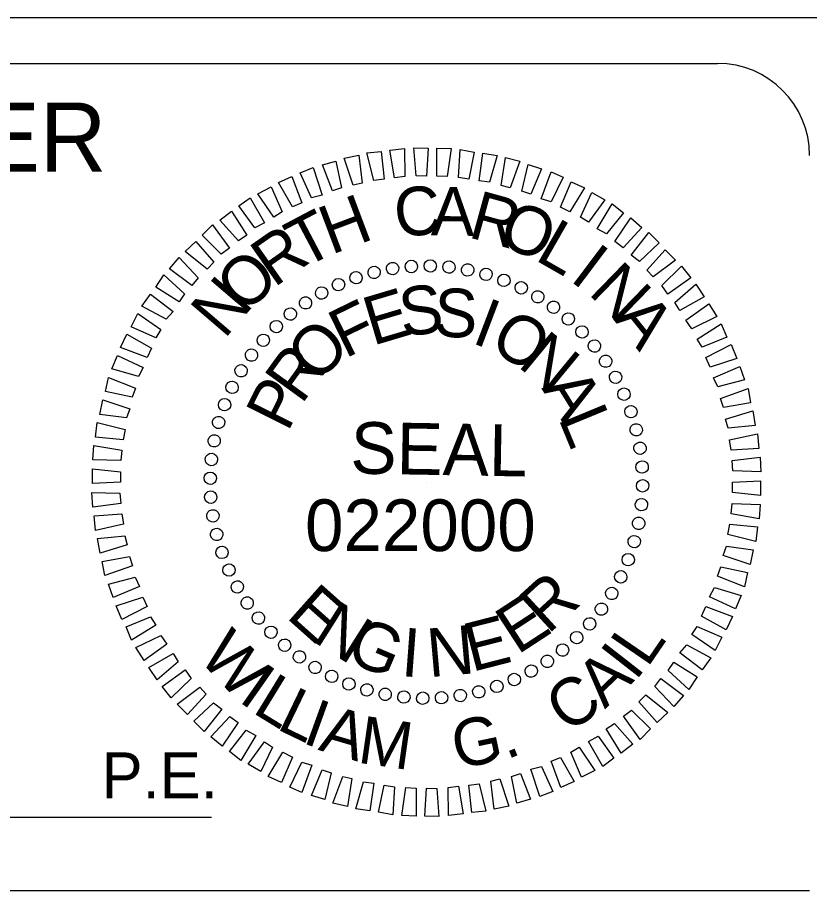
# Model space of a CAD drawing. Extents: x 2163579 to 2286010, y 210234 to 425257.
# Drawn here: x 2253219 to 2258732, y 338718 to 344796 of the extents above; entities that cross this region are included whole.
import ezdxf

# ---------------------------------------------------------------- set-up
doc = ezdxf.new("R2010")
doc.units = 0
doc.layers.add('Sheet Professional Seal CELL', color=7, linetype='Continuous')
doc.layers.add('Sheet Title CELL', color=7, linetype='Continuous')

msp = doc.modelspace()

# ---------------------------------------------------------------- linework, layer by layer
at = {"layer": 'Sheet Professional Seal CELL'}
for p, q in [((2255700, 343022.5), (2255700, 343022.5)), ((2255832, 343046.5), (2255832, 343046.5)), ((2255961, 343064.5), (2255961, 343064.5)), ((2256093, 343067.5), (2256093, 343067.5)), ((2256225, 343058.5), (2256225, 343058.5)), ((2256354, 343037.5), (2256354, 343037.5)), ((2256480, 343010.5), (2256480, 343010.5)), ((2255574, 342986.5), (2255574, 342986.5)), ((2256606, 342968.5), (2256606, 342968.5)), ((2255454, 342938.5), (2255454, 342938.5)), ((2256726, 342914.5), (2256726, 342914.5)), ((2255337, 342878.5), (2255337, 342878.5)), ((2256843, 342854.5), (2256843, 342854.5)), ((2255223, 342809.5), (2255223, 342809.5)), ((2256951, 342779.5), (2256951, 342779.5)), ((2255118, 342734.5), (2255118, 342734.5)), ((2255019, 342644.5), (2255019, 342644.5)), ((2257056, 342698.5), (2257056, 342698.5)), ((2257149, 342608.5), (2257149, 342608.5)), ((2254929, 342551.5), (2254929, 342551.5)), ((2257239, 342509.5), (2257239, 342509.5)), ((2254848, 342446.5), (2254848, 342446.5)), ((2257314, 342404.5), (2257314, 342404.5)), ((2254773, 342338.5), (2254773, 342338.5)), ((2257383, 342290.5), (2257383, 342290.5)), ((2254713, 342221.5), (2254713, 342221.5)), ((2257443, 342173.5), (2257443, 342173.5)), ((2254659, 342101.5), (2254659, 342101.5)), ((2257491, 342053.5), (2257491, 342053.5)), ((2254617, 341975.5), (2254617, 341975.5)), ((2257527, 341927.5), (2257527, 341927.5)), ((2254590, 341849.5), (2254590, 341849.5)), ((2257551, 341795.5), (2257551, 341795.5)), ((2254569, 341720.5), (2254569, 341720.5)), ((2257569, 341666.5), (2257569, 341666.5)), ((2254560, 341588.5), (2254560, 341588.5)), ((2256066, 341561.5), (2256066, 341561.5)), ((2257572, 341534.5), (2257572, 341534.5)), ((2254563, 341456.5), (2254563, 341456.5)), ((2257563, 341402.5), (2257563, 341402.5)), ((2254581, 341327.5), (2254581, 341327.5)), ((2257542, 341273.5), (2257542, 341273.5)), ((2254605, 341195.5), (2254605, 341195.5)), ((2257515, 341147.5), (2257515, 341147.5)), ((2254641, 341069.5), (2254641, 341069.5)), ((2257473, 341021.5), (2257473, 341021.5)), ((2254689, 340949.5), (2254689, 340949.5)), ((2257419, 340901.5), (2257419, 340901.5)), ((2254749, 340832.5), (2254749, 340832.5)), ((2257359, 340784.5), (2257359, 340784.5)), ((2254818, 340718.5), (2254818, 340718.5)), ((2257284, 340676.5), (2257284, 340676.5)), ((2254893, 340613.5), (2254893, 340613.5)), ((2257203, 340571.5), (2257203, 340571.5)), ((2254983, 340514.5), (2254983, 340514.5)), ((2257113, 340478.5), (2257113, 340478.5)), ((2255076, 340424.5), (2255076, 340424.5)), ((2255181, 340343.5), (2255181, 340343.5)), ((2257014, 340388.5), (2257014, 340388.5)), ((2256909, 340313.5), (2256909, 340313.5)), ((2255289, 340268.5), (2255289, 340268.5)), ((2256795, 340244.5), (2256795, 340244.5)), ((2255406, 340208.5), (2255406, 340208.5)), ((2255526, 340154.5), (2255526, 340154.5)), ((2256678, 340184.5), (2256678, 340184.5)), ((2255652, 340112.5), (2255652, 340112.5)), ((2256432, 340100.5), (2256432, 340100.5)), ((2256558, 340136.5), (2256558, 340136.5)), ((2255778, 340085.5), (2255778, 340085.5)), ((2255907, 340064.5), (2255907, 340064.5)), ((2256039, 340055.5), (2256039, 340055.5)), ((2256171, 340058.5), (2256171, 340058.5)), ((2256300, 340076.5), (2256300, 340076.5))]:
    msp.add_line(p, q, dxfattribs=at)
for points in [[(2255700, 343661.5), (2255652, 343853.5), (2255751, 343862.5), (2255772, 343670.5)], [(2255844, 343679.5), (2255811, 343871.5), (2255913, 343883.5), (2255916, 343688.5)], [(2255994, 343694.5), (2255979, 343889.5), (2256078, 343886.5), (2256066, 343691.5)], [(2256138, 343691.5), (2256138, 343886.5), (2256237, 343883.5), (2256210, 343688.5)], [(2256288, 343682.5), (2256300, 343877.5), (2256399, 343859.5), (2256360, 343670.5)], [(2255556, 343628.5), (2255493, 343817.5), (2255595, 343838.5), (2255619, 343643.5)], [(2256432, 343658.5), (2256459, 343850.5), (2256558, 343835.5), (2256504, 343649.5)], [(2256585, 343625.5), (2256615, 343820.5), (2256717, 343796.5), (2256648, 343610.5)], [(2255265, 343541.5), (2255187, 343715.5), (2255277, 343751.5), (2255340, 343559.5)], [(2255412, 343589.5), (2255343, 343769.5), (2255436, 343796.5), (2255475, 343610.5)], [(2256729, 343586.5), (2256774, 343772.5), (2256867, 343742.5), (2256792, 343565.5)], [(2255133, 343478.5), (2255037, 343646.5), (2255130, 343688.5), (2255199, 343505.5)], [(2256864, 343532.5), (2256933, 343721.5), (2257017, 343685.5), (2256933, 343511.5)], [(2255004, 343406.5), (2254893, 343568.5), (2254986, 343616.5), (2255061, 343442.5)], [(2256999, 343475.5), (2257074, 343652.5), (2257167, 343610.5), (2257065, 343442.5)], [(2257137, 343406.5), (2257218, 343577.5), (2257308, 343526.5), (2257194, 343370.5)], [(2254872, 343331.5), (2254761, 343484.5), (2254839, 343541.5), (2254938, 343367.5)], [(2257254, 343325.5), (2257359, 343499.5), (2257437, 343436.5), (2257320, 343289.5)], [(2254758, 343241.5), (2254629, 343385.5), (2254710, 343448.5), (2254815, 343280.5)], [(2257377, 343235.5), (2257488, 343400.5), (2257566, 343334.5), (2257434, 343193.5)], [(2254638, 343148.5), (2254506, 343280.5), (2254578, 343352.5), (2254695, 343190.5)], [(2257491, 343142.5), (2257614, 343298.5), (2257686, 343226.5), (2257548, 343097.5)], [(2254539, 343043.5), (2254386, 343166.5), (2254461, 343235.5), (2254587, 343091.5)], [(2257599, 343037.5), (2257728, 343178.5), (2257800, 343106.5), (2257644, 342989.5)], [(2254434, 342929.5), (2254278, 343046.5), (2254344, 343124.5), (2254476, 342983.5)], [(2257704, 342929.5), (2257842, 343064.5), (2257905, 342983.5), (2257746, 342869.5)], [(2254344, 342815.5), (2254182, 342917.5), (2254239, 343004.5), (2254383, 342872.5)], [(2257794, 342812.5), (2257941, 342938.5), (2257998, 342851.5), (2257830, 342755.5)], [(2254254, 342695.5), (2254086, 342785.5), (2254146, 342869.5), (2254302, 342749.5)], [(2257872, 342689.5), (2258031, 342803.5), (2258088, 342713.5), (2257914, 342629.5)], [(2254182, 342566.5), (2254011, 342641.5), (2254056, 342734.5), (2254218, 342623.5)], [(2257950, 342557.5), (2258118, 342662.5), (2258157, 342569.5), (2257986, 342500.5)], [(2254122, 342428.5), (2253936, 342497.5), (2253981, 342590.5), (2254152, 342494.5)], [(2258010, 342428.5), (2258187, 342518.5), (2258226, 342422.5), (2258040, 342362.5)], [(2254062, 342296.5), (2253876, 342350.5), (2253915, 342443.5), (2254095, 342359.5)], [(2258064, 342287.5), (2258247, 342365.5), (2258280, 342272.5), (2258094, 342224.5)], [(2254017, 342152.5), (2253831, 342191.5), (2253852, 342290.5), (2254041, 342215.5)], [(2258112, 342143.5), (2258304, 342212.5), (2258322, 342113.5), (2258133, 342080.5)], [(2253978, 342008.5), (2253792, 342032.5), (2253813, 342134.5), (2254002, 342071.5)], [(2258148, 341999.5), (2258337, 342056.5), (2258355, 341954.5), (2258166, 341936.5)], [(2253954, 341855.5), (2253762, 341873.5), (2253774, 341975.5), (2253969, 341927.5)], [(2258175, 341855.5), (2258370, 341897.5), (2258379, 341795.5), (2258187, 341783.5)], [(2253939, 341711.5), (2253744, 341717.5), (2253750, 341816.5), (2253945, 341783.5)], [(2258193, 341711.5), (2258388, 341735.5), (2258394, 341633.5), (2258199, 341639.5)], [(2253936, 341561.5), (2253741, 341552.5), (2253741, 341654.5), (2253936, 341633.5)], [(2258196, 341561.5), (2258391, 341570.5), (2258391, 341468.5), (2258196, 341489.5)], [(2253939, 341411.5), (2253744, 341387.5), (2253738, 341489.5), (2253933, 341483.5)], [(2258193, 341411.5), (2258388, 341405.5), (2258382, 341306.5), (2258187, 341339.5)], [(2253957, 341267.5), (2253762, 341225.5), (2253753, 341327.5), (2253945, 341339.5)], [(2258178, 341267.5), (2258370, 341249.5), (2258358, 341147.5), (2258163, 341195.5)], [(2253984, 341123.5), (2253795, 341066.5), (2253777, 341168.5), (2253966, 341186.5)], [(2258154, 341114.5), (2258340, 341090.5), (2258319, 340988.5), (2258130, 341051.5)], [(2254020, 340979.5), (2253828, 340910.5), (2253810, 341009.5), (2253999, 341042.5)], [(2258115, 340970.5), (2258301, 340931.5), (2258280, 340832.5), (2258091, 340907.5)], [(2254068, 340835.5), (2253885, 340757.5), (2253852, 340850.5), (2254038, 340898.5)], [(2258070, 340826.5), (2258256, 340772.5), (2258217, 340679.5), (2258037, 340763.5)], [(2254122, 340694.5), (2253945, 340604.5), (2253906, 340700.5), (2254092, 340760.5)], [(2258010, 340694.5), (2258196, 340625.5), (2258151, 340532.5), (2257980, 340628.5)], [(2254182, 340565.5), (2254014, 340460.5), (2253975, 340553.5), (2254146, 340622.5)], [(2257950, 340556.5), (2258121, 340481.5), (2258076, 340388.5), (2257914, 340499.5)], [(2254260, 340433.5), (2254101, 340319.5), (2254044, 340409.5), (2254218, 340493.5)], [(2257878, 340427.5), (2258046, 340337.5), (2257986, 340253.5), (2257830, 340373.5)], [(2254338, 340310.5), (2254191, 340184.5), (2254134, 340271.5), (2254302, 340367.5)], [(2257788, 340307.5), (2257950, 340205.5), (2257893, 340118.5), (2257749, 340250.5)], [(2254428, 340193.5), (2254290, 340058.5), (2254227, 340139.5), (2254386, 340253.5)], [(2257698, 340193.5), (2257854, 340076.5), (2257788, 339998.5), (2257656, 340139.5)], [(2254533, 340085.5), (2254404, 339944.5), (2254332, 340016.5), (2254488, 340133.5)], [(2257593, 340079.5), (2257746, 339956.5), (2257671, 339887.5), (2257545, 340031.5)], [(2254641, 339980.5), (2254518, 339824.5), (2254446, 339896.5), (2254584, 340025.5)], [(2257494, 339974.5), (2257626, 339842.5), (2257554, 339770.5), (2257437, 339932.5)], [(2254755, 339887.5), (2254644, 339722.5), (2254566, 339788.5), (2254698, 339929.5)], [(2257374, 339881.5), (2257503, 339737.5), (2257422, 339674.5), (2257317, 339842.5)], [(2254878, 339797.5), (2254773, 339623.5), (2254695, 339686.5), (2254812, 339833.5)], [(2257260, 339791.5), (2257371, 339638.5), (2257293, 339581.5), (2257194, 339755.5)], [(2254995, 339716.5), (2254914, 339545.5), (2254824, 339596.5), (2254938, 339752.5)], [(2255133, 339647.5), (2255058, 339470.5), (2254965, 339512.5), (2255067, 339680.5)], [(2257128, 339716.5), (2257239, 339554.5), (2257146, 339506.5), (2257071, 339680.5)], [(2255268, 339590.5), (2255199, 339401.5), (2255115, 339437.5), (2255199, 339611.5)], [(2256999, 339644.5), (2257095, 339476.5), (2257002, 339434.5), (2256933, 339617.5)], [(2255403, 339536.5), (2255358, 339350.5), (2255265, 339380.5), (2255340, 339557.5)], [(2256867, 339581.5), (2256945, 339407.5), (2256855, 339371.5), (2256792, 339563.5)], [(2255547, 339497.5), (2255517, 339302.5), (2255415, 339326.5), (2255484, 339512.5)], [(2256576, 339494.5), (2256639, 339305.5), (2256537, 339284.5), (2256513, 339479.5)], [(2256720, 339533.5), (2256789, 339353.5), (2256696, 339326.5), (2256657, 339512.5)], [(2255700, 339464.5), (2255673, 339272.5), (2255574, 339287.5), (2255628, 339473.5)], [(2255844, 339440.5), (2255832, 339245.5), (2255733, 339263.5), (2255772, 339452.5)], [(2255994, 339431.5), (2255994, 339236.5), (2255895, 339239.5), (2255922, 339434.5)], [(2256138, 339428.5), (2256153, 339233.5), (2256054, 339236.5), (2256066, 339431.5)], [(2256288, 339443.5), (2256321, 339251.5), (2256219, 339239.5), (2256216, 339434.5)], [(2256432, 339461.5), (2256480, 339269.5), (2256381, 339260.5), (2256360, 339452.5)]]:
    msp.add_lwpolyline(points, close=True, dxfattribs=at)
for centre, major_axis in [((2255701.9, 343021.6), (-10.5, 41.9)), ((2255830.6, 343047.8), (-6.8, 42.7)), ((2255961, 343062.6), (-3, 43.1)), ((2256092.2, 343066.1), (0.8, 43.2)), ((2256223.2, 343058), (4.5, 43)), ((2256353.1, 343038.6), (8.2, 42.4)), ((2255576, 342984.3), (-14.1, 40.8)), ((2256480.7, 343008), (11.9, 41.5)), ((2256605.2, 342966.3), (15.5, 40.3)), ((2255453.9, 342936.2), (-17.6, 39.5)), ((2256725.6, 342914), (18.9, 38.8)), ((2255336.4, 342877.6), (-20.9, 37.8)), ((2256841, 342851.4), (22.2, 37)), ((2255224.5, 342809), (-24.2, 35.8)), ((2256950.5, 342778.9), (25.4, 34.9)), ((2255119, 342730.9), (-27.2, 33.6)), ((2257053.2, 342697.2), (28.3, 32.6)), ((2255020.6, 342644), (-30, 31.1)), ((2257148.4, 342606.8), (31.1, 30)), ((2254930.3, 342548.7), (-32.6, 28.3)), ((2257235.4, 342508.5), (33.6, 27.2)), ((2254848.5, 342446), (-34.9, 25.4)), ((2257313.5, 342403), (35.8, 24.2)), ((2254776.1, 342336.5), (-37, 22.2)), ((2257382.1, 342291), (37.8, 20.9)), ((2254713.4, 342221.2), (-38.8, 18.9)), ((2257440.7, 342173.5), (39.5, 17.6)), ((2254661.1, 342100.8), (-40.3, 15.5)), ((2257488.8, 342051.4), (40.8, 14.1)), ((2254619.4, 341976.3), (-41.5, 11.9)), ((2257526.1, 341925.5), (41.9, 10.5)), ((2254588.8, 341848.6), (-42.4, 8.2)), ((2257552.2, 341796.9), (42.7, 6.8)), ((2254569.4, 341718.8), (-43, 4.5)), ((2257567.1, 341666.5), (43.1, 3)), ((2254561.4, 341587.8), (-43.2, 0.8)), ((2257570.5, 341535.2), (43.2, -0.8)), ((2254564.8, 341456.5), (-43.1, -3)), ((2257562.5, 341404.2), (43, -4.5)), ((2254579.7, 341326.1), (-42.7, -6.8)), ((2257543.1, 341274.4), (42.4, -8.2)), ((2254605.9, 341197.4), (-41.9, -10.5)), ((2257512.5, 341146.7), (41.5, -11.9)), ((2254643.1, 341071.6), (-40.8, -14.1)), ((2257470.8, 341022.2), (40.3, -15.5)), ((2254691.3, 340949.4), (-39.5, -17.6)), ((2257418.5, 340901.8), (38.8, -18.9)), ((2254749.8, 340831.9), (-37.8, -20.9)), ((2257355.8, 340786.5), (37, -22.2)), ((2254818.4, 340720), (-35.8, -24.2)), ((2257283.4, 340677), (34.9, -25.4)), ((2254896.5, 340614.5), (-33.6, -27.2)), ((2257201.6, 340574.3), (32.6, -28.3)), ((2254983.5, 340516.2), (-31.1, -30)), ((2257111.3, 340479), (30, -31.1)), ((2255078.7, 340425.8), (-28.3, -32.6)), ((2257013, 340392), (27.2, -33.6)), ((2255181.5, 340344.1), (-25.4, -34.9)), ((2256907.4, 340314), (24.2, -35.8)), ((2255290.9, 340271.6), (-22.2, -37)), ((2256795.5, 340245.4), (20.9, -37.8)), ((2255406.3, 340209), (-18.9, -38.8)), ((2256678, 340186.8), (17.6, -39.5)), ((2255526.7, 340156.6), (-15.5, -40.3)), ((2255651.2, 340115), (-11.9, -41.5)), ((2256555.9, 340138.7), (14.1, -40.8)), ((2255778.8, 340084.3), (-8.2, -42.4)), ((2255908.7, 340064.9), (-4.5, -43)), ((2256039.7, 340056.9), (-0.8, -43.2)), ((2256170.9, 340060.4), (3, -43.1)), ((2256301.4, 340075.2), (6.8, -42.7)), ((2256430, 340101.4), (10.5, -41.9))]:
    msp.add_ellipse(centre, major_axis=major_axis, ratio=0.999708, dxfattribs=at)
at = {"layer": 'Sheet Title CELL'}
for p, q in [((2178427, 344796.3), (2269307, 344796.3)), ((2245307, 344476.3), (2258092.3, 344476.3)), ((2245338.6, 339228.9), (2254570.6, 339228.9)), ((2244609.4, 338717.8), (2258732.2, 338717.8))]:
    msp.add_line(p, q, dxfattribs=at)
msp.add_arc((2258092.3, 343836.3), 640, 0, 90, dxfattribs=at)

# ---------------------------------------------------------------- texts
at = {"layer": 'Sheet Professional Seal CELL'}
for s, height, rotation, p in [('C', 338.3, 6.21987, (2255859, 343262.5)), ('A', 338.3, 359.02032, (2256096, 343280.5)), ('H', 338.3, 20.61948, (2255403, 343142.5)), ('R', 338.3, 344.6211, (2256348, 343268.5)), ('O', 338.3, 337.42116, (2256549, 343223.5)), ('T', 338.3, 27.81977, (2255208, 343043.5)), ('L', 338.3, 330.22088, (2256813, 343112.5)), ('R', 338.3, 35.02051, (2255004, 342911.5)), ('I', 338.3, 323.02014, (2257056, 342968.5)), ('O', 338.3, 42.22174, (2254797, 342725.5)), ('N', 338.3, 315.81891, (2257185, 342875.5)), ('N', 338.3, 49.4235, (2254659, 342551.5)), ('E', 338.3, 16.61107, (2255691, 342509.5)), ('S', 338.3, 7.25561, (2255898, 342572.5)), ('S', 338.3, 357.9004, (2256114, 342575.5)), ('F', 338.3, 25.96703, (2255499, 342419.5)), ('I', 338.3, 339.1896, (2256372, 342533.5)), ('A', 338.3, 308.61715, (2257362, 342698.5)), ('O', 338.3, 329.83348, (2256492, 342491.5)), ('O', 338.3, 44.68124, (2255301, 342242.5)), ('N', 338.3, 320.47661, (2256693, 342371.5)), ('R', 338.3, 54.03965, (2255196, 342095.5)), ('P', 338.4, 63.39889, (2255100, 341903.5)), ('A', 338.3, 301.76027, (2256864, 342215.5)), ('L', 338.4, 292.40085, (2256981, 342008.5)), ('SEAL', 359.89, 359, (2255535, 341621.5)), ('R', 338.3, 42.48141, (2256912, 340496.5)), ('E', 338.3, 318.27689, (2255082, 340622.5)), ('E', 338.3, 33.12409, (2256699, 340355.5)), ('N', 338.3, 327.63396, (2255262, 340460.5)), ('G', 338.3, 336.99024, (2255490, 340325.5)), ('E', 338.3, 14.41176, (2256381, 340238.5)), ('W', 330, 313.33495, (2254470.8, 340335.2)), ('I', 338.3, 355.7012, (2255883, 340211.5)), ('N', 338.3, 5.05639, (2256084, 340202.5)), ('L', 330, 55.60016, (2257603.2, 340263.2)), ('I', 330, 52.07969, (2257520.5, 340171.3)), ('A', 330, 43.8939, (2257307.8, 339978.3)), ('I', 330, 324.94103, (2254750.1, 340039.3)), ('L', 330, 328.4615, (2254846.1, 339961.4)), ('C', 330, 35.02118, (2257048.7, 339805.8)), ('L', 330, 334.2717, (2255014.3, 339846.1)), ('I', 330, 340.08189, (2255193.4, 339748.5)), ('A', 330, 343.60236, (2255306.3, 339698.3)), ('M', 330, 351.78815, (2255579.4, 339609.1)), ('G', 330, 11.90919, (2256280.7, 339560.9)), ('.', 330, 21.8409, (2256622.5, 339627.9))]:
    msp.add_text(s, height=height, rotation=rotation, dxfattribs=at).set_placement(p)
msp.add_text('022000', height=359.89, dxfattribs=at).set_placement((2255220.9, 341081))
at = {"layer": 'Sheet Title CELL'}
for s, height, p in [(' HYDRAULICS ENGINEER', 480, (2245991.8, 343723.5)), ('P.E.', 319.97, (2253805.2, 339359.8))]:
    msp.add_text(s, height=height, rotation=360, dxfattribs=at).set_placement(p)

doc.saveas('drawing.dxf')
